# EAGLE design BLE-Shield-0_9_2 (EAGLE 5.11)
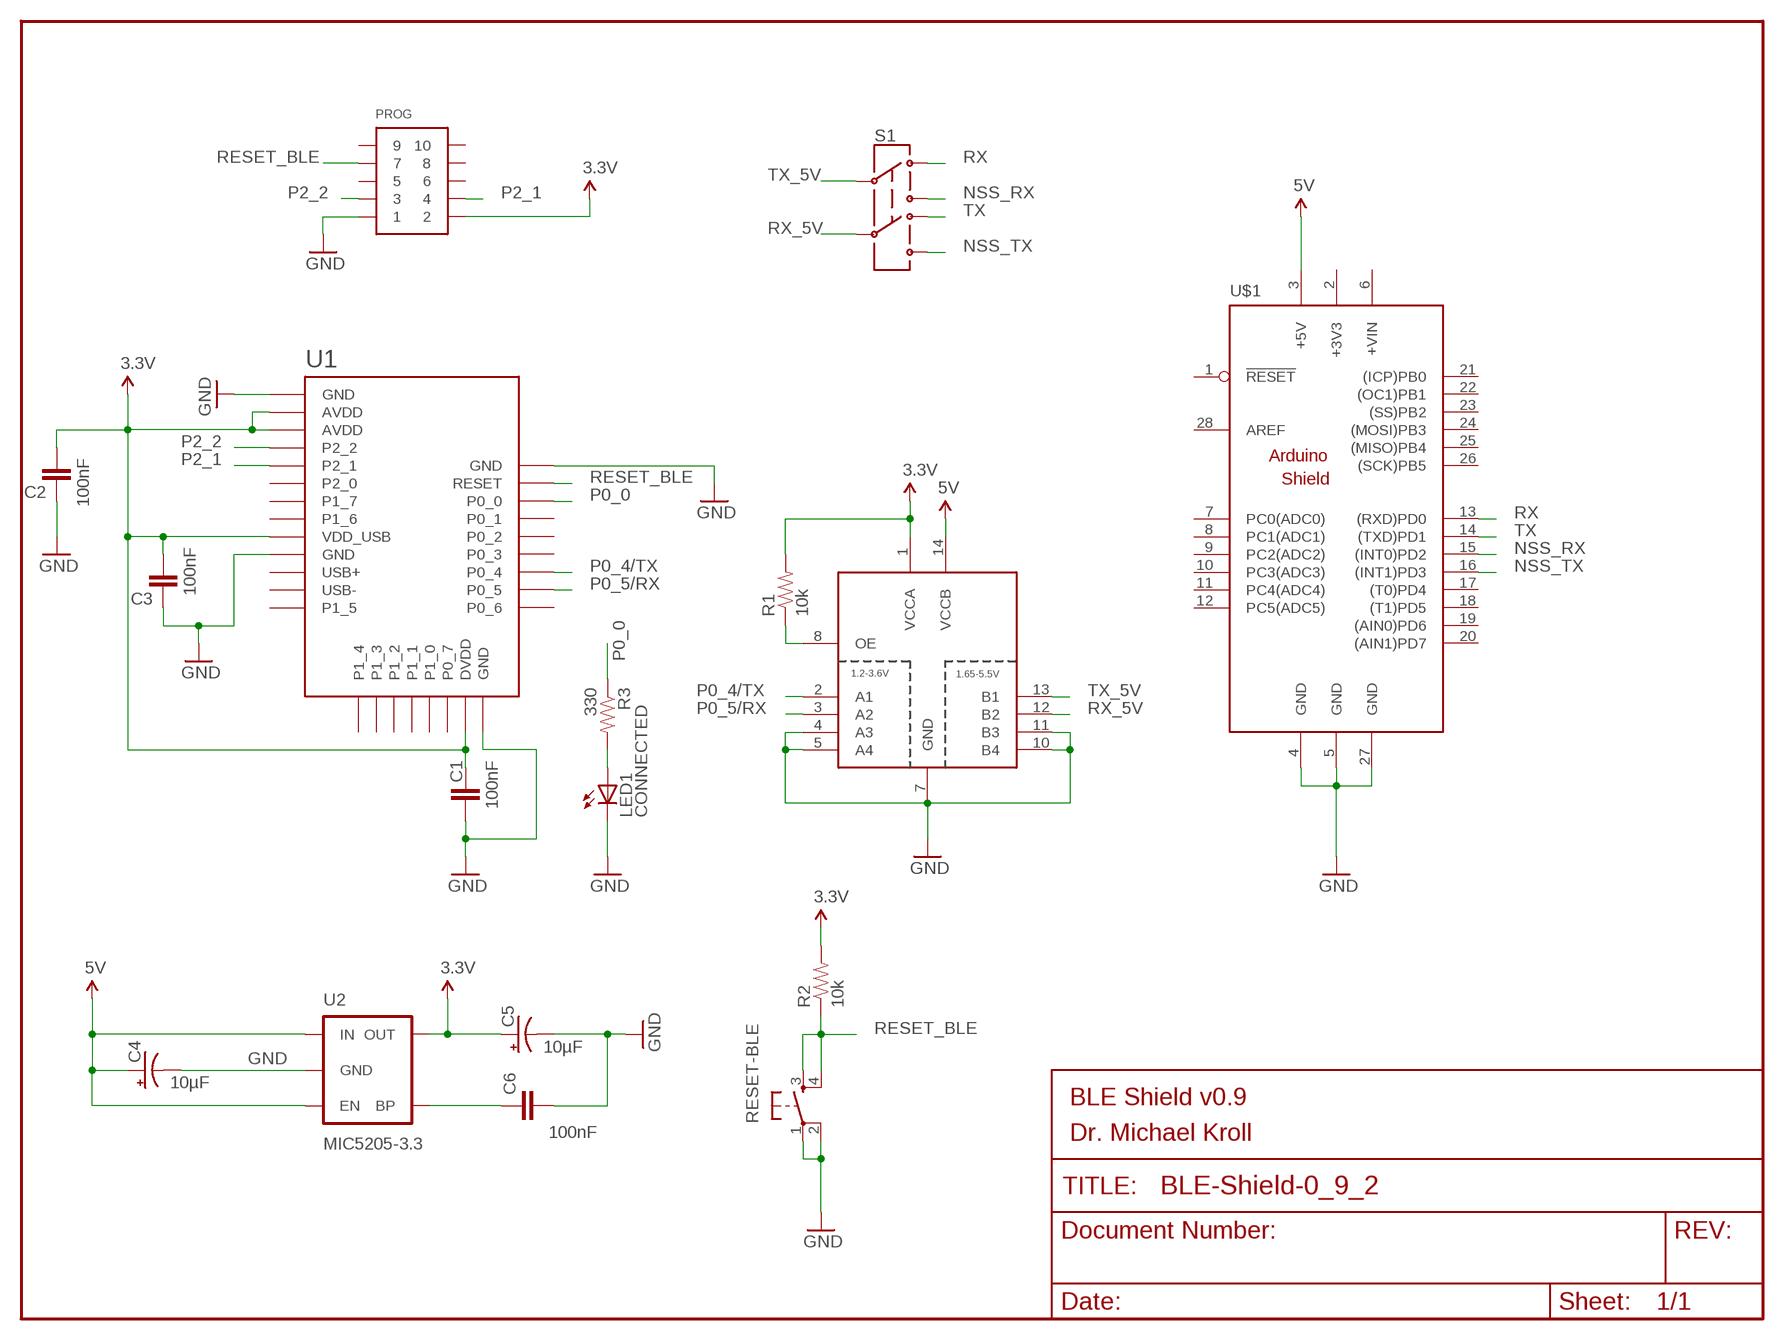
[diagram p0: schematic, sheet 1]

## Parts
C1  100nF  CAP1206  [1206]
C2  100nF  CAP1206  [1206]
C3  100nF  CAP1206  [1206]
C4  10µF  CAP_POL1206  [EIA3216]
C5  10µF  CAP_POL1206  [EIA3216]
C6  100nF  CAP1206  [1206]
LED1  CONNECTED  LED1206-BLUE  [LED-1206-BLUE]
PROG  CONN_5-2-FTSH-V  [FTSH-105-DV]
R1  10k  RESISTOR0805-RES  [0805]
R2  10k  RESISTOR0805-RES  [0805]
R3  330  RESISTOR0805-RES  [0805]
RESET-BLE  TAC_SWITCHSMD  [TACTILE_SWITCH_SMD]
S1  SWITCH-DPDTSMD  [AYZ0202]
U1  BLE112-A-VISUAL  [BLE112-A]
U2  MIC5205-3.3  V_REG_LDOSMD  [SOT23-5]
U3  TXB0104DR  [SO14]
U$1  ARDUINO_SHIELD  [ARDUINO_SHIELD]

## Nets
3.3V: C1.2 C2.2 C3.2 C5.A(+) PROG.2 R1.2 R2.2 U1.AVDD1(AVDD) U1.AVDD2(AVDD) U1.DVDD U1.VDD_USB U2.5(OUT) U3.1(VCCA)
5V: C4.A(+) U2.1(IN) U2.3(EN) U3.14(VCCB) U$1.3(+5V)
GND: C1.1 C2.1 C3.1 C4.C(-) C5.C(-) C6.2 LED1.C PROG.1 RESET-BLE.1 RESET-BLE.2 U1.GND1(GND) U1.GND2(GND) U1.GND3(GND) U1.GND4(GND) U2.2(GND) U3.4(A3) U3.5(A4) U3.7(GND) U3.10(B4) U3.11(B3) U$1.4(GND) U$1.5(GND) U$1.27(GND)
N$2: C6.1 U2.4(BP)
N$4: LED1.A R3.2
N$6: R1.1 U3.8(OE)
NSS_RX: S1.3 U$1.15((INT0)PD2)
NSS_TX: S1.6 U$1.16((INT1)PD3)
P0_0: R3.1 U1.P0_0
P0_4/TX: U1.P0_4 U3.2(A1)
P0_5/RX: U1.P0_5 U3.3(A2)
P2_1: PROG.4 U1.P2_1
P2_2: PROG.3 U1.P2_2
RESET_BLE: PROG.7 R2.1 RESET-BLE.3 RESET-BLE.4 U1.RESET
RX: S1.1 U$1.13((RXD)PD0)
RX_5V: S1.5 U3.12(B2)
TX: S1.4 U$1.14((TXD)PD1)
TX_5V: S1.2 U3.13(B1)
Unconnected: PROG.5 PROG.6 PROG.8 PROG.9 PROG.10 U1.P0_1 U1.P0_2 U1.P0_3 U1.P0_6 U1.P0_7 U1.P1_0 U1.P1_1 U1.P1_2 U1.P1_3 U1.P1_4 U1.P1_5 U1.P1_6 U1.P1_7 U1.P2_0 U1.USB+ U1.USB- U$1.1(!RESET) U$1.6(+VIN) U$1.7(PC0(ADC0)) U$1.8(PC1(ADC1)) U$1.9(PC2(ADC2)) U$1.10(PC3(ADC3)) U$1.11(PC4(ADC4)) U$1.12(PC5(ADC5)) U$1.17((T0)PD4) U$1.18((T1)PD5) U$1.19((AIN0)PD6) U$1.20((AIN1)PD7) U$1.21((ICP)PB0) U$1.22((OC1)PB1) U$1.23((SS)PB2) U$1.24((MOSI)PB3) U$1.25((MISO)PB4) U$1.26((SCK)PB5) U$1.28(AREF)

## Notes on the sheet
- BLE Shield v0.9
- Dr. Michael Kroll

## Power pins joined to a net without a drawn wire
+3V3: U$1.2(+3V3)

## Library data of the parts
C1-C3 C6 = SparkFun:CAP: Capacitor
C4 C5 = SparkFun:CAP_POL: Capacitor Polarized
LED1 = SparkFun:LED: LEDs
PROG = pel_misc:CONN_5-2
R1-R3 = SparkFun:RESISTOR: Resistor
RESET-BLE = SparkFun:TAC_SWITCH: Momentary Switch Button commonly used for reset or general input. Spark Fun Electronics SKU : COM-00097
S1 = SparkFun:SWITCH-DPDT: DPDT Version of the COM-00597
U1 = sf-bluegiga:BLE112-A-VISUAL: Bluetooth Low Energy single-mode module - Bluetooth 4.0, chip antenna
U2 = SparkFun:V_REG_LDO: Voltage Regulator LDO Standard 150mA LDO voltage regulator in SOT-23 layout. Micrel part MIC5205. BP (by-pass) pin is used to lower output noise with 470pF cap.
U3 = Software-Culture-Parts:TXB0104DR: 4-Bit Bi-Directional Level Shifter 1.2V-3.6V (VCCA) to 1.65V-5.5V (VCCB) bi-directional level shifter with auto direction sensing. Max data rate - VCCA 1.8V: 20Mbps (50ns), VCCA 3.3V: 100Mbps (10ns) Digikey: 296-21929-1-ND
U$1 = arduino:ARDUINO_SHIELD: Arduino Shield

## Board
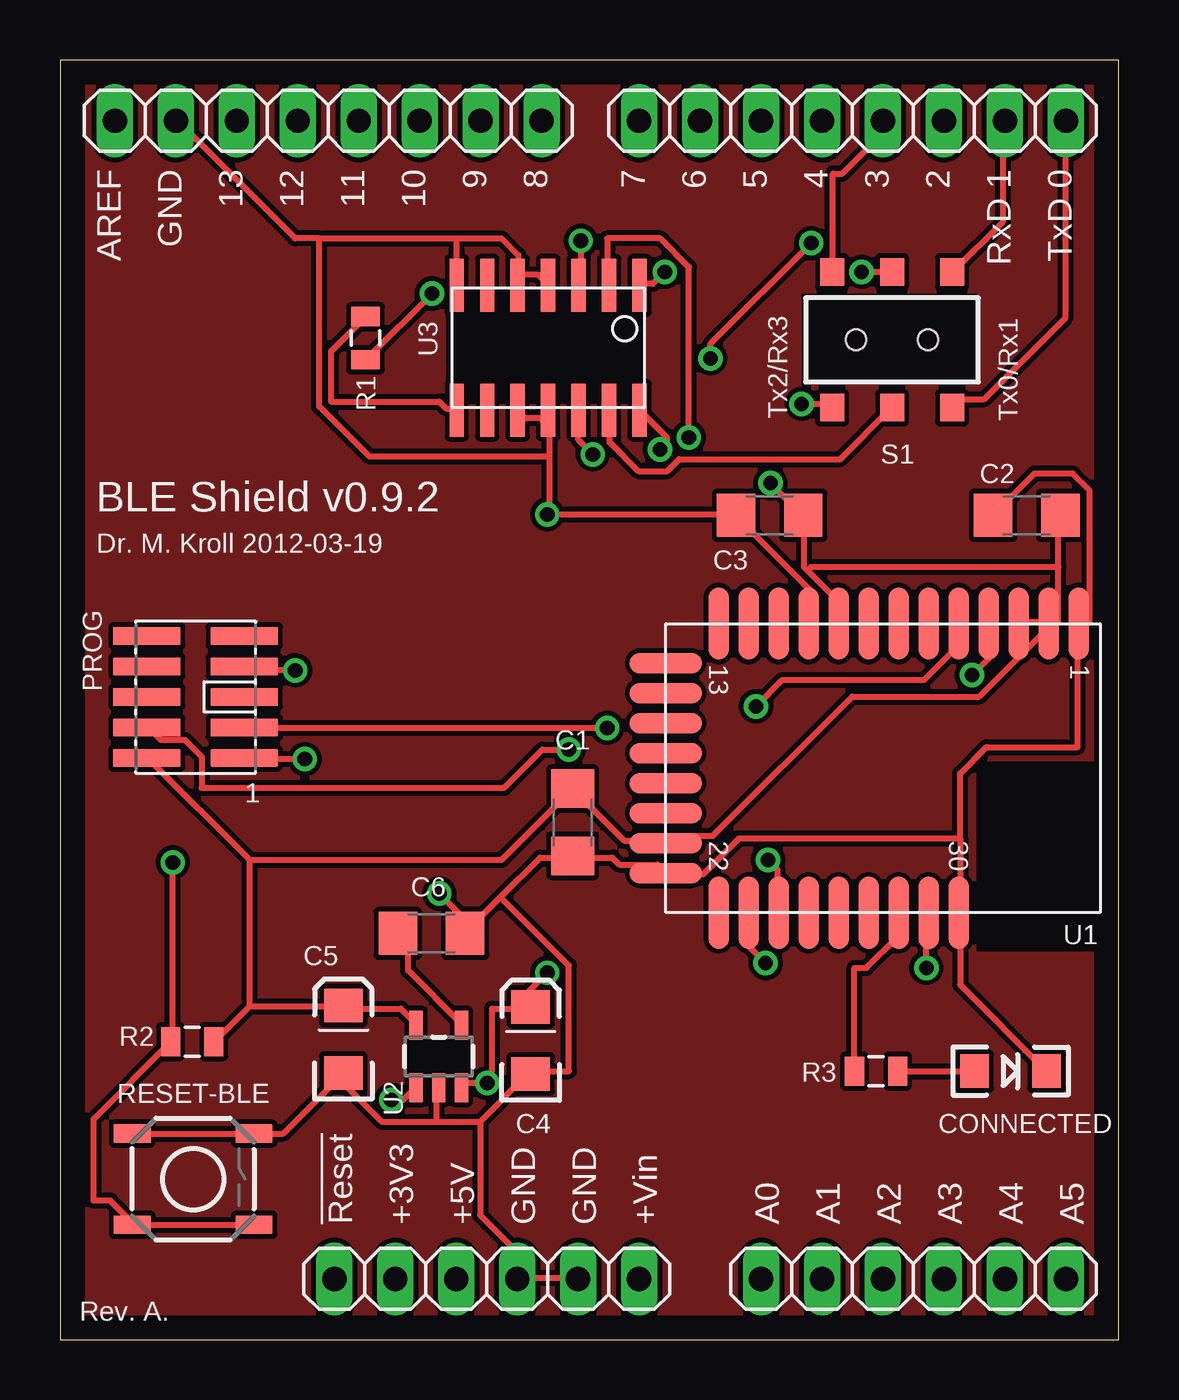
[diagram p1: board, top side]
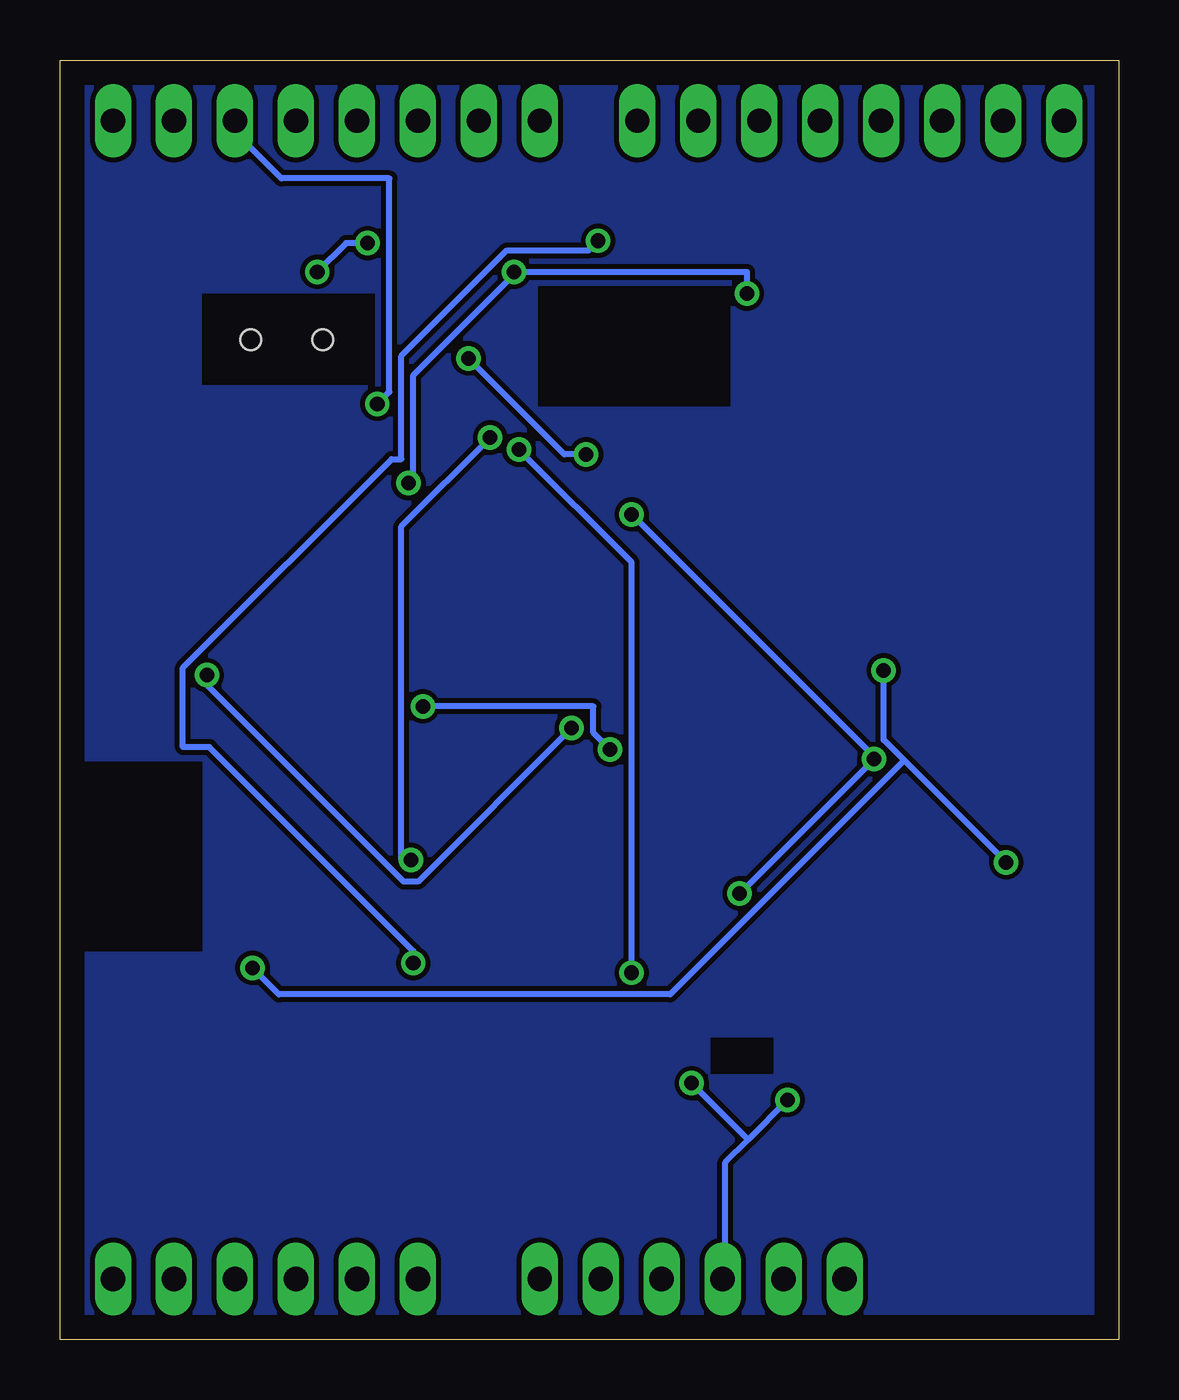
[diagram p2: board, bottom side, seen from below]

Size 44.12 x 53.33 mm. Coordinates in mm from the lower left corner, seen from the top.
Outline: 0,0 44.12,0 44.12,53.33 0,53.33 0,0
Copper layers (1*16): Top 0.035mm / dielectric 1.5mm / Bottom 0.035mm
Design rules "default": minimum track width 10mil, minimum drill 24mil, track to track 8mil, track to pad 8mil, pad to pad 8mil, via to via 8mil, smd to smd 8mil, copper to edge 40mil, drill to drill 8mil, minimum pad ring 10mil, minimum via ring 8mil, stop-mask expansion 4mil, vias tented up to drill 0mil, thermal gap 10mil
tRestrict: area 38.2,16.2 to 44,24.1; area 30.9,39.8 to 38.2,43.6; area 16.1,39 to 24.3,43.8; area 14.4,11.1 to 17.2,12.5
bRestrict: area 38.2,16.2 to 44,24.1; area 31,39.8 to 38.2,43.6; area 16.2,38.9 to 24.2,43.9; area 14.4,11.1 to 17,12.6

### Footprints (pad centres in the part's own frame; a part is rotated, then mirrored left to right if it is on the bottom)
1206 = smd 1.6 x 1.8: 1 -1.4,0; 2 1.4,0
EIA3216 = smd 1.4 x 1.6: A 1.4,0; C -1.4,0
LED-1206-BLUE = smd 1.2 x 1.4: A -1.5,0; C 1.5,0
FTSH-105-DV = smd 0.74 x 2.8: 1 -2.54,-2.03; 2 -2.54,2.03; 3 -1.27,-2.03; 4 -1.27,2.03; 5 0,-2.03; 6 0,2.03; 7 1.27,-2.03; 8 1.27,2.03; 9 2.54,-2.03; 10 2.54,2.03
0805 = smd 0.8 x 1.2: 1 -0.9,0; 2 0.9,0
TACTILE_SWITCH_SMD = smd 1.524 x 0.762: 1 -2.54,1.905; 2 2.54,1.905; 3 -2.54,-1.905; 4 2.54,-1.905
AYZ0202 = smd 1 x 1.15: 1 -2.5,2.825; 2 0,2.825; 3 2.5,2.825; 4 -2.5,-2.825; 5 0,-2.825; 6 2.5,-2.825 | hole 0.85: 1.5,0; -1.5,0
BLE112-A = smd 3 x 0.85: AVDD1 -6.05,6.9; AVDD2 -6.05,5.65; GND1 -6.05,8.15; GND2 -6.05,-3.1; GND4 6,3.15; P0_0 6,0.65; P0_1 6,-0.6; P0_2 6,-1.85; P0_3 6,-3.1; P0_4 6,-4.35; P0_5 6,-5.6; P0_6 6,-6.85; P1_5 -6.05,-6.85; P1_6 -6.05,-0.6; P1_7 -6.05,0.65; P2_0 -6.05,1.9; P2_1 -6.05,3.15; P2_2 -6.05,4.4; RESET 6,1.9; USB+ -6.05,-4.35; USB- -6.05,-5.6; VDD_USB -6.05,-1.85 | smd 0.85 x 3: DVDD 3.1,-9.05; GND3 4.35,-9.05; P0_7 1.85,-9.05; P1_0 0.6,-9.05; P1_1 -0.65,-9.05; P1_2 -1.9,-9.05; P1_3 -3.15,-9.05; P1_4 -4.4,-9.05
SOT23-5 = smd 0.55 x 1.2: 1 -0.95,-1.3; 2 0,-1.3; 3 0.95,-1.3; 4 0.95,1.3; 5 -0.95,1.3
SO14 = smd 0.6 x 2.2: 1 -3.81,-2.6; 2 -2.54,-2.6; 3 -1.27,-2.6; 4 0,-2.6; 5 1.27,-2.6; 6 2.54,-2.6; 7 3.81,-2.6; 8 3.81,2.6; 9 2.54,2.6; 10 1.27,2.6; 11 0,2.6; 12 -1.27,2.6; 13 -2.54,2.6; 14 -3.81,2.6
ARDUINO_SHIELD = drill 1.016 long: 1 19.05,-8.89; 2 21.59,-8.89; 3 24.13,-8.89; 4 26.67,-8.89; 5 29.21,-8.89; 6 31.75,-8.89; 7 36.83,-8.89; 8 39.37,-8.89; 9 41.91,-8.89; 10 44.45,-8.89; 11 46.99,-8.89; 12 49.53,-8.89; 13 49.53,39.37; 14 46.99,39.37; 15 44.45,39.37; 16 41.91,39.37; 17 39.37,39.37; 18 36.83,39.37; 19 34.29,39.37; 20 31.75,39.37; 21 27.686,39.37; 22 25.146,39.37; 23 22.606,39.37; 24 20.066,39.37; 25 17.526,39.37; 26 14.986,39.37; 27 12.446,39.37; 28 9.906,39.37

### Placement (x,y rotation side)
C1  21.36,21.57 90 top
C2  40.28,34.36 0 top
C3  29.57,34.36 0 top
C4  19.61,12.48 90 top
C5  11.81,12.53 90 top
C6  15.48,16.94 0 top
LED1  39.6,11.2 0 top
PROG  5.65,26.79 90 top
R1  12.73,41.74 270 top
R2  5.51,12.43 0 top
R3  34,11.2 0 top
RESET-BLE  5.55,6.7 0 top
S1  34.67,41.67 180 top
U1  34.29,23.8 270 top
U2  15.78,11.81 0 top
U3  20.34,41.34 180 top
U$1  -7.62,11.43 0 top

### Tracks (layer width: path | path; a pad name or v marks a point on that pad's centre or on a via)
3.3V  (via drill 0.61)
  Top 0.254: 7.9,13.9 6.5,12.5 R2.2 | 7.9,13.9 11.8,13.9 C5.A 11.8,13.8 14.2,13.8 14.8,13.2 U2.5 | 7.9,20 3.7,24.2 PROG.2 | 7.9,13.9 7.9,20 | 7.9,20 18.4,20 21.3,22.9 C1.2 21.4,22.9 23.5,20.8 25.1,20.8 25.2,20.7 U1.DVDD 25.3,20.8 25.5,21 27.2,21 33,26.8 38.3,26.8 41.3,29.8 U1.AVDD1 | v15.5,43.6 12.8,40.9 R1.2 | v25.2,44.5 24.7,44 24.2,44 U3.1 | 31.15,32.05 32.4,30.8 32.4,29.9 U1.VDD_USB | 31.15,32.05 31,32.2 31,34.3 C3.2 30.9,34.4 v29.6,35.7 | 41.6,32.2 41.6,29.9 41.2,29.9 U1.AVDD1 | 41.6,32.2 41.6,34.3 C2.2 | U1.AVDD2 40,29.9 41.1,29.9 U1.AVDD1 | 31.15,32.05 31.3,32.2 41.6,32.2
  Bottom 0.254: v15.5,43.6 15.5,44.5 v25.2,44.5 25.2,44.4 29.4,40.2 29.4,35.7 v29.6,35.7
5V  (via drill 0.61)
  Top 0.254: v13.8,10 14.3,10 14.8,10.5 U2.1 | 17.65,10.85 18,11.2 18,13.8 19.6,13.8 C4.A 18.9,13.9 v20.3,15.3 | 17.65,10.85 17.5,10.7 16.9,10.7 16.8,10.6 U2.3 | v25,37.1 25.3,37.1 25.3,37.6 24.2,38.7 U3.14 | v17.8,10.7 17.65,10.85
  Bottom 0.254: 15.45,8.35 16.4,7.4 16.4,2.6 16.5,2.6 U$1.3 | 15.45,8.35 v13.8,10 | v25,37.1 20.3,32.4 v20.3,15.3 | 15.45,8.35 v17.8,10.7
GND  (via drill 0.61)
  Top 0.254: U3.10 19.1,38.7 19.4,38.4 20.1,38.4 20.4,38.7 U3.11 20.1,38.3 20.4,38 20.4,36.8 | U1.GND2 31.2,29.9 31.2,31.3 28.2,34.3 C3.1 28.1,34.4 20.4,34.4 | 20.4,34.4 20.4,36.8 | 16.5,45.9 16.5,44 U3.7 | 16.5,45.9 18.4,45.9 19.1,45.2 19.1,44 U3.5 19.2,44.4 19.9,44.4 20.3,44 U3.4 | 10.8,45.9 9.8,45.9 4.9,50.8 U$1.27 | 10.8,45.9 16.5,45.9 | 20.4,36.8 12.9,36.8 10.8,38.9 10.8,45.9 | C2.1 38.9,34.4 40.6,36.1 42.2,36.1 42.9,35.4 42.9,29.9 42.5,29.9 U1.GND1 42.4,29.8 42.4,24.7 38.6,24.7 37.5,23.6 37.5,20.9 | LED1.C 37.5,14.8 37.5,17.8 U1.GND4 37.5,17.9 37.5,20.9 | 18.35,18.45 20,20.1 21.3,20.1 C1.1 21.4,20.1 23,20.1 23.3,19.8 24.9,19.8 25.2,19.5 U1.GND3 25.3,19.4 26.8,19.4 28.3,20.9 37.5,20.9 | 18.35,18.45 16.9,17 C6.2 17.1,17.3 v15.8,18.6 | v10.2,24.2 7.7,24.2 PROG.1 | U$1.5 21.5,2.6 19.1,2.6 U$1.4 19.1,2.7 19.1,3.9 18.8,3.9 17.5,5.2 17.5,9.1 | 15.7,9.1 15.7,10.5 U2.2 | 15.7,9.1 17.5,9.1 | 17.5,9.1 19.4,11 19.6,11 C4.C 19.6,11.2 21.2,11.2 21.2,15.6 18.35,18.45 | RESET-BLE.1 3.1,8.6 8,8.6 RESET-BLE.2 8.2,8.6 9.3,8.6 11.8,11.1 C5.C 11.6,10.8 11.7,10.8 13.4,9.1 15.7,9.1 | v20.3,34.4 20.4,34.4
  Bottom 0.254: v15.8,18.6 v10.2,24.2 10.2,24.3 v20.3,34.4
N$1
  pour Bottom: 0,53.3 44.1,53.3 44.1,0 0,0
N$2
  Top 0.254: U2.4 16.7,13.2 14.5,15.4 14.5,16.9 14.1,16.9 C6.1
N$3
  pour Top: 0,53.3 44.1,53.3 44.1,0 0,0
N$4
  Top 0.254: R3.2 LED1.A
N$6
  Top 0.254: R1.1 12.7,42.6 11.3,41.2 11.3,39.1 15.8,39.1 16.1,38.8 16.5,38.8 U3.8
NSS_RX  (via drill 0.61)
  Top 0.254: v30.9,39 32,39 32.1,38.9 S1.3
  Bottom 0.254: v30.9,39 30.4,39.5 30.4,48.4 34.9,48.4 36.8,50.3 36.8,50.8 U$1.15
NSS_TX
  Top 0.254: S1.6 32.2,44.5 32.2,48.6 32.6,48.6 34.2,50.2 34.2,50.8 U$1.16
P0_0
  Top 0.254: R3.1 33.1,15.5 33.6,15.5 34.9,16.8 34.9,17.8 U1.P0_0
P0_4/TX  (via drill 0.61)
  Top 0.254: v26.2,37.6 26.2,44.7 25,45.9 22.8,45.9 22.8,44 U3.2 | v29.5,20 29.9,19.6 29.9,17.8 U1.P0_4
  Bottom 0.254: v26.2,37.6 29.9,33.9 29.9,20 v29.5,20
P0_5/RX  (via drill 0.61)
  Top 0.254: v21.7,45.8 21.7,44 U3.3 | v29.4,15.7 28.7,16.4 U1.P0_5
  Bottom 0.254: v21.7,45.8 22.1,45.4 25.5,45.4 29.9,41 29.9,36.7 30.3,36.7 39,28 39,24.7 37.9,24.7 29.4,16.2 v29.4,15.7
P2_1  (via drill 0.61)
  Top 0.254: v21.2,24.6 20.1,24.6 18.5,23 5.9,23 5.9,24.3 5.2,25 4.2,25 3.7,25.5 PROG.4 | v29,26.4 30.1,27.5 36,27.5 37.4,28.9 37.4,29.8 U1.P2_1
  Bottom 0.254: v21.2,24.6 21.9,25.3 21.9,26.4 v29,26.4
P2_2  (via drill 0.61)
  Top 0.254: v22.8,25.5 7.7,25.5 PROG.3 | v38,27.7 38.7,28.4 38.7,29.8 U1.P2_2
  Bottom 0.254: v22.8,25.5 29.2,19.1 29.8,19.1 38,27.3 v38,27.7
RESET_BLE  (via drill 0.61)
  Top 0.254: RESET-BLE.4 8,4.8 3.2,4.8 RESET-BLE.3 3.1,4.8 2.1,5.8 1.4,5.8 1.4,9.2 4.6,12.4 R2.1 4.7,12.5 v4.7,19.9 | v9.8,27.9 7.8,27.9 7.7,28 PROG.7 | v36.1,15.5 36.1,17.8 U1.RESET
  Bottom 0.254: v9.8,27.9 9.8,25 8.95,24.15 | v4.7,19.9 8.95,24.15 | v36.1,15.5 35,14.4 18.7,14.4 8.95,24.15
RX
  Top 0.254: S1.1 37.2,38.9 37.5,39.2 38.5,39.2 41.9,42.6 U$1.13
RX_5V  (via drill 0.61)
  Top 0.254: v33.4,44.5 34.6,44.5 S1.5 | v31.3,45.7 27.1,41.5 v27.1,40.9 | v22.2,36.9 21.6,37.5 21.6,38.7 U3.12
  Bottom 0.254: v33.4,44.5 32.2,45.7 v31.3,45.7 | v27.1,40.9 23.1,36.9 v22.2,36.9
TX
  Top 0.254: S1.4 37.2,44.5 39.3,46.6 39.3,50.8 U$1.14
TX_5V
  Top 0.254: S1.2 34.6,38.8 32.5,36.7 25.8,36.7 25.3,36.2 24.1,36.2 22.9,37.4 22.9,38.7 U3.13

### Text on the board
tNames: Tx2/Rx3 | Tx0/Rx1 | BLE Shield v0.9.2 | Dr. M. Kroll 2012-03-19 | 1 | Rev. A.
